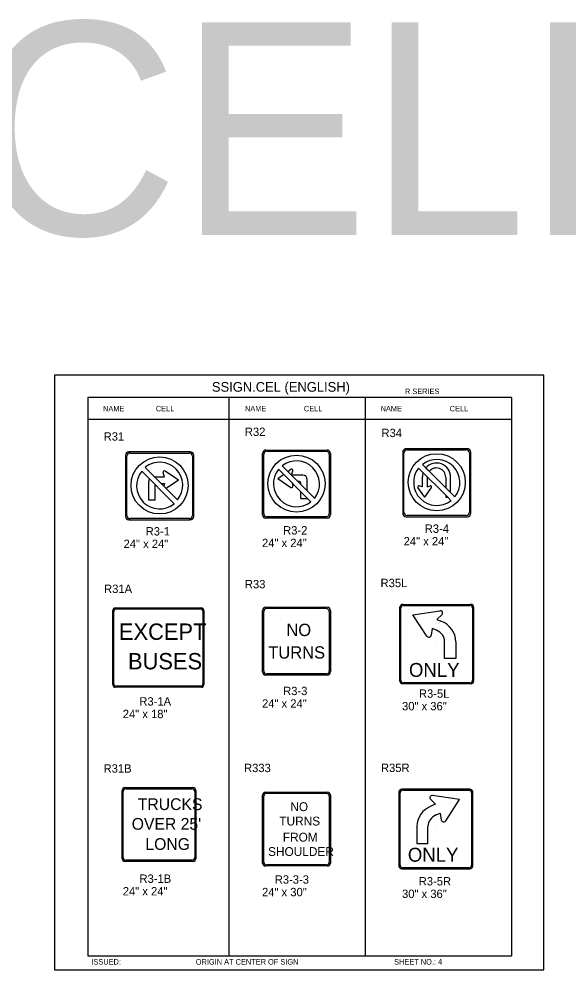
# Model space of a CAD drawing. Extents: x -5299 to 22597, y -19549 to -1808.
# Drawn here: x -2878 to -2090, y -3623 to -2261 of the extents above; entities that cross this region are included whole.
import ezdxf

# ---------------------------------------------------------------- set-up
doc = ezdxf.new("R2010")
doc.units = 0
for name, color, linetype in [('Level 1', 7, 'Continuous'), ('Level 2', 7, 'Continuous'), ('Level 3', 7, 'Continuous'), ('Level 63', 7, 'Continuous')]:
    doc.layers.add(name, color=color, linetype=linetype)

msp = doc.modelspace()

# ---------------------------------------------------------------- linework, layer by layer
at = {"layer": 'Level 1'}
for p, q in [((-2172.6, -2802.9), (-2779.6, -2802.9)), ((-2779.6, -2802.9), (-2779.6, -3602.9)), ((-2577.3, -2802.9), (-2577.3, -3602.9)), ((-2382.2, -2802.9), (-2382.2, -3602.9)), ((-2172.6, -2802.9), (-2172.6, -3602.9)), ((-2172.6, -2834.6), (-2779.6, -2834.6)), ((-2723.4, -2971.9), (-2723.4, -2887)), ((-2718.9, -2882.5), (-2634, -2882.5)), ((-2629.5, -2887), (-2629.5, -2971.9)), ((-2527.4, -2969.3), (-2527.4, -2884.4)), ((-2522.9, -2879.9), (-2438, -2879.9)), ((-2433.5, -2884.4), (-2433.5, -2969.3)), ((-2326.5, -2967.4), (-2326.5, -2882.5)), ((-2322, -2878), (-2237.1, -2878)), ((-2232.6, -2882.5), (-2232.6, -2967.4)), ((-2464.5, -2937.1), (-2500.9, -2900.9)), ((-2493, -2908.7), (-2500.9, -2900.9)), ((-2263.6, -2935.1), (-2300, -2899)), ((-2292.1, -2906.8), (-2300, -2899)), ((-2701.9, -2908.3), (-2655.7, -2955.1)), ((-2650.8, -2949.6), (-2697.1, -2903)), ((-2669.5, -2916.6), (-2671.4, -2910.6)), ((-2649.7, -2921.2), (-2668.4, -2908.3)), ((-2507.2, -2918.7), (-2499.1, -2913.1)), ((-2506.4, -2905.8), (-2464.7, -2947.6)), ((-2492.7, -2908.7), (-2488.5, -2905.8)), ((-2487.4, -2914.1), (-2485.5, -2908.1)), ((-2471.2, -2914.1), (-2487.4, -2914.1)), ((-2305.5, -2903.9), (-2263.8, -2945.6)), ((-2692, -2950.2), (-2692, -2923)), ((-2683.5, -2916.6), (-2669.5, -2916.6)), ((-2682.9, -2950.2), (-2682.9, -2927.6)), ((-2676.5, -2929.4), (-2676.5, -2929.4)), ((-2674.4, -2925.9), (-2669.7, -2925.9)), ((-2669.7, -2925.9), (-2670.7, -2929.5)), ((-2649.7, -2921.2), (-2667, -2933.2)), ((-2507.2, -2918.7), (-2488.5, -2931.7)), ((-2486.6, -2925.7), (-2485.5, -2929.3)), ((-2480.4, -2926.9), (-2480.4, -2926.9)), ((-2480.4, -2926.9), (-2480.4, -2926.9)), ((-2476.2, -2923.3), (-2478.3, -2923.3)), ((-2474, -2927.5), (-2474, -2925.4)), ((-2464.9, -2936.7), (-2464.9, -2920.4)), ((-2300.2, -2930.8), (-2304.8, -2929.3)), ((-2300.2, -2917.1), (-2300.2, -2930.8)), ((-2293.3, -2917.1), (-2293.3, -2930.8)), ((-2293.3, -2930.8), (-2288.8, -2929.3)), ((-2279.5, -2924.9), (-2279.5, -2924.9)), ((-2266.6, -2917.1), (-2266.6, -2932.1)), ((-2259.6, -2939.2), (-2259.6, -2917.1)), ((-2474, -2947.7), (-2474, -2938.2)), ((-2454.4, -2947.3), (-2464.6, -2937.2)), ((-2454.4, -2947.3), (-2464.6, -2937.2)), ((-2296.7, -2945.7), (-2306.4, -2931.7)), ((-2296.7, -2945.7), (-2287, -2931.7)), ((-2266.6, -2942.9), (-2266.6, -2945.7)), ((-2253.6, -2945.4), (-2263.7, -2935.3)), ((-2253.6, -2945.4), (-2263.7, -2935.3)), ((-2682.9, -2950.2), (-2692, -2950.2)), ((-2474, -2947.7), (-2464.9, -2947.7)), ((-2464.9, -2947.7), (-2464.9, -2947.5)), ((-2464.6, -2947.5), (-2459.9, -2952.3)), ((-2266.6, -2945.7), (-2264, -2945.7)), ((-2264, -2945.7), (-2264, -2945.6)), ((-2263.7, -2945.6), (-2259.1, -2950.3)), ((-2634, -2976.4), (-2718.9, -2976.4)), ((-2438, -2973.8), (-2522.9, -2973.8)), ((-2237.1, -2971.9), (-2322, -2971.9)), ((-2739.2, -3105.7), (-2617.6, -3105.7)), ((-2438, -3105.1), (-2522.9, -3105.1)), ((-2330.8, -3208.3), (-2330.8, -3104.3)), ((-2326.9, -3100.8), (-2232.2, -3100.8)), ((-2228.3, -3104.3), (-2228.3, -3208.3)), ((-2742.2, -3213.1), (-2742.2, -3109.2)), ((-2614.6, -3109.2), (-2614.6, -3213.1)), ((-2527.4, -3194.5), (-2527.4, -3109.6)), ((-2433.5, -3109.6), (-2433.5, -3194.5)), ((-2313.6, -3114.3), (-2274.9, -3108.4)), ((-2293.7, -3144.8), (-2313.6, -3114.3)), ((-2271.8, -3113.6), (-2279.2, -3120.8)), ((-2285.9, -3133.8), (-2287.3, -3143.5)), ((-2279.9, -3136.2), (-2285.9, -3133.8)), ((-2279.2, -3120.8), (-2273.4, -3123.2)), ((-2480.4, -3152), (-2480.4, -3152)), ((-2279.5, -3156.3), (-2279.5, -3156.3)), ((-2268.2, -3176.9), (-2268.2, -3152.8)), ((-2252.3, -3152.9), (-2252.3, -3176.9)), ((-2678.4, -3161.1), (-2678.4, -3161.1)), ((-2252.3, -3176.9), (-2268.2, -3176.9)), ((-2438, -3199), (-2522.9, -3199)), ((-2232.2, -3211.8), (-2326.9, -3211.8)), ((-2617.6, -3216.6), (-2739.2, -3216.6)), ((-2724.8, -3363.4), (-2630.1, -3363.4)), ((-2728.7, -3462.1), (-2728.7, -3367.4)), ((-2626.2, -3367.4), (-2626.2, -3462.1)), ((-2527.4, -3468.7), (-2527.4, -3374)), ((-2522.9, -3370), (-2438, -3370)), ((-2433.5, -3374), (-2433.5, -3468.7)), ((-2332, -3473.1), (-2332, -3369.1)), ((-2328.1, -3365.6), (-2233.4, -3365.6)), ((-2288.5, -3378.4), (-2281.1, -3385.6)), ((-2246.7, -3379.1), (-2285.5, -3373.2)), ((-2266.6, -3409.6), (-2246.7, -3379.1)), ((-2229.5, -3369.1), (-2229.5, -3473.1)), ((-2281.1, -3385.6), (-2286.9, -3388)), ((-2280.4, -3401), (-2274.4, -3398.6)), ((-2274.4, -3398.6), (-2273, -3408.3)), ((-2677.4, -3414.7), (-2677.4, -3414.7)), ((-2308, -3417.7), (-2308, -3441.7)), ((-2292.2, -3441.7), (-2292.2, -3417.6)), ((-2480.4, -3421.3), (-2480.4, -3421.3)), ((-2280.8, -3421.1), (-2280.8, -3421.1)), ((-2308, -3441.7), (-2292.2, -3441.7)), ((-2630.1, -3466), (-2724.8, -3466)), ((-2438, -3472.6), (-2522.9, -3472.6)), ((-2233.4, -3476.6), (-2328.1, -3476.6)), ((-2779.6, -3602.9), (-2172.6, -3602.9))]:
    msp.add_line(p, q, dxfattribs=at)
for centre in [(-2676.5, -2928.8), (-2480.4, -2926.3), (-2279.5, -2924.3)]:
    msp.add_circle(centre, 40.9, dxfattribs=at)
for centre, radius, start, end in [((-2718.9, -2887), 4.51, 90, 180), ((-2634, -2887), 4.51, 0, 90), ((-2522.9, -2884.4), 4.51, 90, 180), ((-2438, -2884.4), 4.51, 0, 90), ((-2322, -2882.5), 4.51, 90, 180), ((-2237.1, -2882.5), 4.51, 0, 90), ((-2676.5, -2928.8), 33.1, 321.0482, 128.591), ((-2480.4, -2926.9), 33.1, 321.7522, 128.2478), ((-2279.5, -2924.9), 33.1, 321.7522, 128.2478), ((-2279.9, -2917.1), 20.3, 0, 139.3838), ((-2676.5, -2929.4), 33.1, 140.291, 308.9542), ((-2669.5, -2910), 2.03, 58.3416, 196.1912), ((-2480.4, -2926.3), 33.1, 141.7575, 308.2425), ((-2487.4, -2907.5), 2.03, 343.8088, 121.6584), ((-2471.2, -2920.4), 6.31, 0, 90), ((-2279.5, -2924.4), 33.1, 141.7575, 308.2425), ((-2279.9, -2917.1), 20.3, 160.5218, 180), ((-2279.9, -2917.1), 13.3, 0, 140.8143), ((-2685.7, -2923), 6.31, 145.8302, 180), ((-2487.4, -2929.9), 2.03, 238.3416, 16.1912), ((-2476.2, -2925.4), 2.1, 0, 90), ((-2305.1, -2930.8), 1.53, 73.8088, 211.6584), ((-2279.9, -2917.1), 13.3, 174.9338, 180), ((-2288.3, -2930.8), 1.53, 328.3416, 106.1912), ((-2522.9, -2969.3), 4.51, 180, 270), ((-2438, -2969.3), 4.51, 270, 0), ((-2322, -2967.4), 4.51, 180, 270), ((-2237.1, -2967.4), 4.51, 270, 0), ((-2718.9, -2971.9), 4.51, 180, 270), ((-2634, -2971.9), 4.51, 270, 0), ((-2522.9, -3109.6), 4.51, 90, 180), ((-2438, -3109.6), 4.51, 0, 90), ((-2522.9, -3194.5), 4.51, 180, 270), ((-2438, -3194.5), 4.51, 270, 0), ((-2724.8, -3367.4), 3.91, 90, 180), ((-2630.1, -3367.4), 3.91, 0, 90), ((-2724.8, -3462.1), 3.91, 180, 270), ((-2630.1, -3462.1), 3.91, 270, 0)]:
    msp.add_arc(centre, radius, start, end, dxfattribs=at)
for centre, major_axis, ratio, start_param, end_param in [((-2739.2, -3109.2), (0, -3.51), 0.857082, 3.141593, 4.712389), ((-2617.6, -3109.2), (0, 3.51), 0.857082, 4.712389, 6.283185), ((-2326.9, -3104.3), (-3.91, 0), 0.8975, 4.712389, 6.283185), ((-2232.2, -3104.3), (-3.91, 0), 0.8975, 3.141593, 4.712389), ((-2274.5, -3111.5), (3.51, 0), 0.8975, 5.561964, 7.978205), ((-2288.7, -3152.8), (36.4, 0), 0.8975, 6.282849, 7.423415), ((-2290.8, -3143), (3.51, 0), 0.8975, 3.720842, 6.1394), ((-2288.7, -3152.9), (-20.5, 0), 0.8975, 3.143205, 4.271453), ((-2739.2, -3213.1), (0, -3.51), 0.857082, 4.712389, 6.283185), ((-2617.6, -3213.1), (0, 3.51), 0.857082, 3.141593, 4.712389), ((-2326.9, -3208.3), (3.91, 0), 0.8975, 3.141593, 4.712389), ((-2232.2, -3208.3), (3.91, 0), 0.8975, 4.712389, 6.283185), ((-2522.9, -3374), (-4.51, 0), 0.866667, 4.712389, 6.283185), ((-2438, -3374), (-4.51, 0), 0.866667, 3.141593, 4.712389), ((-2328.1, -3369.1), (-3.91, 0), 0.8975, 4.712389, 6.283185), ((-2285.9, -3376.3), (3.51, 0), 0.8975, 1.446573, 3.862814), ((-2233.4, -3369.1), (-3.91, 0), 0.8975, 3.141593, 4.712389), ((-2271.7, -3417.6), (36.4, 0), 0.8975, 2.001363, 3.141929), ((-2271.6, -3417.7), (-20.5, 0), 0.8975, 5.153325, 6.281573), ((-2269.5, -3407.8), (3.51, 0), 0.8975, 3.285378, 5.703936), ((-2522.9, -3468.7), (4.51, 0), 0.866667, 3.141593, 4.712389), ((-2438, -3468.7), (4.51, 0), 0.866667, 4.712389, 6.283185), ((-2328.1, -3473.1), (3.91, 0), 0.8975, 3.141593, 4.712389), ((-2233.4, -3473.1), (3.91, 0), 0.8975, 4.712389, 6.283185)]:
    msp.add_ellipse(centre, major_axis=major_axis, ratio=ratio, start_param=start_param, end_param=end_param, dxfattribs=at)
at = {"layer": 'Level 3'}
for p, q in [((-2725.2, -2885.5), (-2725.2, -2973.3)), ((-2632.6, -2880.7), (-2720.4, -2880.7)), ((-2627.7, -2973.3), (-2627.7, -2885.5)), ((-2529.2, -2970.8), (-2529.2, -2883)), ((-2524.3, -2878.1), (-2436.5, -2878.1)), ((-2431.7, -2883), (-2431.7, -2970.8)), ((-2328.3, -2881.1), (-2328.3, -2968.8)), ((-2235.6, -2876.2), (-2323.4, -2876.2)), ((-2230.8, -2968.8), (-2230.8, -2881.1)), ((-2720.4, -2978.2), (-2632.6, -2978.2)), ((-2436.5, -2975.6), (-2524.3, -2975.6)), ((-2323.4, -2973.7), (-2235.6, -2973.7)), ((-2740.2, -3104.2), (-2616.6, -3104.2)), ((-2524.3, -3103.3), (-2436.5, -3103.3)), ((-2332.4, -3209.4), (-2332.4, -3103.2)), ((-2328.1, -3099.4), (-2230.9, -3099.4)), ((-2226.7, -3103.2), (-2226.7, -3209.4)), ((-2743.4, -3214.2), (-2743.4, -3108)), ((-2613.4, -3108), (-2613.4, -3214.2)), ((-2529.2, -3195.9), (-2529.2, -3108.1)), ((-2431.7, -3108.1), (-2431.7, -3195.9)), ((-2436.5, -3200.8), (-2524.3, -3200.8)), ((-2230.9, -3213.2), (-2328.1, -3213.2)), ((-2616.6, -3218), (-2740.2, -3218)), ((-2726, -3361.9), (-2628.8, -3361.9)), ((-2232.2, -3364.2), (-2329.4, -3364.2)), ((-2730.3, -3463.3), (-2730.3, -3366.1)), ((-2624.6, -3366.1), (-2624.6, -3463.3)), ((-2529.2, -3469.9), (-2529.2, -3372.7)), ((-2524.3, -3368.5), (-2436.5, -3368.5)), ((-2431.7, -3372.7), (-2431.7, -3469.9)), ((-2333.6, -3368), (-2333.6, -3474.2)), ((-2228, -3474.2), (-2228, -3368)), ((-2628.8, -3467.5), (-2726, -3467.5)), ((-2436.5, -3474.1), (-2524.3, -3474.1)), ((-2329.4, -3478), (-2232.2, -3478))]:
    msp.add_line(p, q, dxfattribs=at)
for centre, radius, start, end in [((-2720.4, -2885.5), 4.88, 90, 180), ((-2632.6, -2885.5), 4.88, 0, 90), ((-2524.3, -2883), 4.88, 90, 180), ((-2436.5, -2883), 4.88, 0, 90), ((-2323.4, -2881.1), 4.88, 90, 180), ((-2235.6, -2881.1), 4.88, 0, 90), ((-2323.4, -2968.8), 4.88, 180, 270), ((-2235.6, -2968.8), 4.88, 270, 0), ((-2720.4, -2973.3), 4.88, 180, 270), ((-2632.6, -2973.3), 4.88, 270, 0), ((-2524.3, -2970.8), 4.88, 180, 270), ((-2436.5, -2970.8), 4.88, 270, 0), ((-2524.3, -3108.1), 4.88, 90, 180), ((-2436.5, -3108.1), 4.88, 0, 90), ((-2524.3, -3195.9), 4.88, 180, 270), ((-2436.5, -3195.9), 4.88, 270, 0), ((-2726, -3366.1), 4.23, 90, 180), ((-2628.8, -3366.1), 4.23, 0, 90), ((-2726, -3463.3), 4.23, 180, 270), ((-2628.8, -3463.3), 4.23, 270, 0)]:
    msp.add_arc(centre, radius, start, end, dxfattribs=at)
for centre, major_axis, ratio, start_param, end_param in [((-2740.2, -3108), (0, -3.79), 0.857082, 3.141593, 4.712389), ((-2616.6, -3108), (0, 3.79), 0.857082, 4.712389, 6.283185), ((-2328.1, -3103.2), (-4.23, 0), 0.8975, 4.712389, 6.283185), ((-2230.9, -3103.2), (-4.23, 0), 0.8975, 3.141593, 4.712389), ((-2740.2, -3214.2), (0, -3.79), 0.857082, 4.712389, 6.283185), ((-2616.6, -3214.2), (0, 3.79), 0.857082, 3.141593, 4.712389), ((-2328.1, -3209.4), (4.23, 0), 0.8975, 3.141593, 4.712389), ((-2230.9, -3209.4), (4.23, 0), 0.8975, 4.712389, 6.283185), ((-2329.4, -3368), (-4.23, 0), 0.8975, 4.712389, 6.283185), ((-2232.2, -3368), (-4.23, 0), 0.8975, 3.141593, 4.712389), ((-2524.3, -3372.7), (-4.88, 0), 0.866667, 4.712389, 6.283185), ((-2436.5, -3372.7), (-4.88, 0), 0.866667, 3.141593, 4.712389), ((-2524.3, -3469.9), (4.88, 0), 0.866667, 3.141593, 4.712389), ((-2436.5, -3469.9), (4.88, 0), 0.866667, 4.712389, 6.283185), ((-2329.4, -3474.2), (4.23, 0), 0.8975, 3.141593, 4.712389), ((-2232.2, -3474.2), (4.23, 0), 0.8975, 4.712389, 6.283185)]:
    msp.add_ellipse(centre, major_axis=major_axis, ratio=ratio, start_param=start_param, end_param=end_param, dxfattribs=at)
at = {"layer": 'Level 63'}
msp.add_lwpolyline([(-2827.1, -3623.1), (-2126.1, -3623.1), (-2126.1, -2770.8), (-2827.1, -2770.8)], close=True, dxfattribs=at)

# ---------------------------------------------------------------- texts
at = {"layer": 'Level 1'}
for s, height, p in [('EXCEPT', 23.41, (-2734.8, -3150.1)), ('NO', 17.68, (-2494.9, -3144.7)), ('TURNS', 17.68, (-2520.9, -3177)), ('BUSES', 23.41, (-2721.8, -3192.4)), ('ONLY', 19.91, (-2319.3, -3203.2)), ('TRUCKS', 16.85, (-2707.8, -3394)), ('NO', 12.68, (-2489.2, -3395.5)), ("OVER 25'", 16.85, (-2716.5, -3422.2)), ('TURNS', 12.68, (-2505, -3416.1)), ('FROM', 12.68, (-2500, -3439.2)), ('LONG', 16.85, (-2696.9, -3451.1)), ('SHOULDER', 12.68, (-2521.1, -3459.8)), ('ONLY', 19.91, (-2320.9, -3468))]:
    msp.add_text(s, height=height, dxfattribs=at).set_placement(p)
at = {"layer": 'Level 2'}
for s, p in [('R32', (-2554.4, -2858)), ('R34', (-2358.7, -2859.6)), ('R31', (-2756.7, -2864.7)), ('R33', (-2554.4, -3076.3)), ('R35L', (-2360, -3074.6)), ('R31A', (-2756.1, -3083)), ('R31B', (-2756.8, -3340.4)), ('R333', (-2555.6, -3339.6)), ('R35R', (-2359.4, -3339.5))]:
    msp.add_text(s, height=12, dxfattribs=at).set_placement(p)
at = {"layer": 'Level 3'}
for s, height, p in [('R-SERIES CELLS', 304.775, (-4981.6, -2569.9)), ('SSIGN.CEL (ENGLISH)', 13.857, (-2601.6, -2794.6)), ('R SERIES', 7.92, (-2325.1, -2798)), ('NAME', 7.92, (-2757.6, -2822.8)), ('CELL', 7.92, (-2681.9, -2822.8)), ('NAME', 7.92, (-2554.2, -2822.8)), ('CELL', 7.92, (-2469.8, -2822.8)), ('NAME', 7.92, (-2359.9, -2822.8)), ('CELL', 7.92, (-2261, -2822.8)), ('R3-1', 12, (-2696.5, -3000.6)), ('R3-2', 12, (-2499.6, -2999.2)), ('R3-4', 12, (-2296.7, -2996.8)), ('24" x 24"', 12, (-2728.2, -3018.6)), ('24" x 24"', 12, (-2529.8, -3017.2)), ('24" x 24"', 12, (-2326.9, -3014.8)), ('R3-3', 12, (-2499.6, -3229.3)), ('R3-5L', 12, (-2305, -3233.1)), ('R3-1A', 12, (-2705.6, -3244.3)), ('24" x 24"', 12, (-2529.8, -3247.3)), ('30" x 36"', 12, (-2329.2, -3251.1)), ('24" x 18"', 12, (-2729.3, -3262.3)), ('R3-1B', 12, (-2705.4, -3498.3)), ('R3-3-3', 12, (-2511.6, -3499.5)), ('R3-5R', 12, (-2305.3, -3502)), ('24" x 24"', 12, (-2729.3, -3516.3)), ('24" x 30"', 12, (-2529.8, -3517.5)), ('30" x 36"', 12, (-2329.2, -3520)), ('ISSUED:', 7.92, (-2774.3, -3615.4)), ('ORIGIN AT CENTER OF SIGN', 7.918, (-2624.7, -3615.4)), ('SHEET NO.: 4', 7.918, (-2340.6, -3615.4))]:
    msp.add_text(s, height=height, dxfattribs=at).set_placement(p)

doc.saveas('drawing.dxf')
